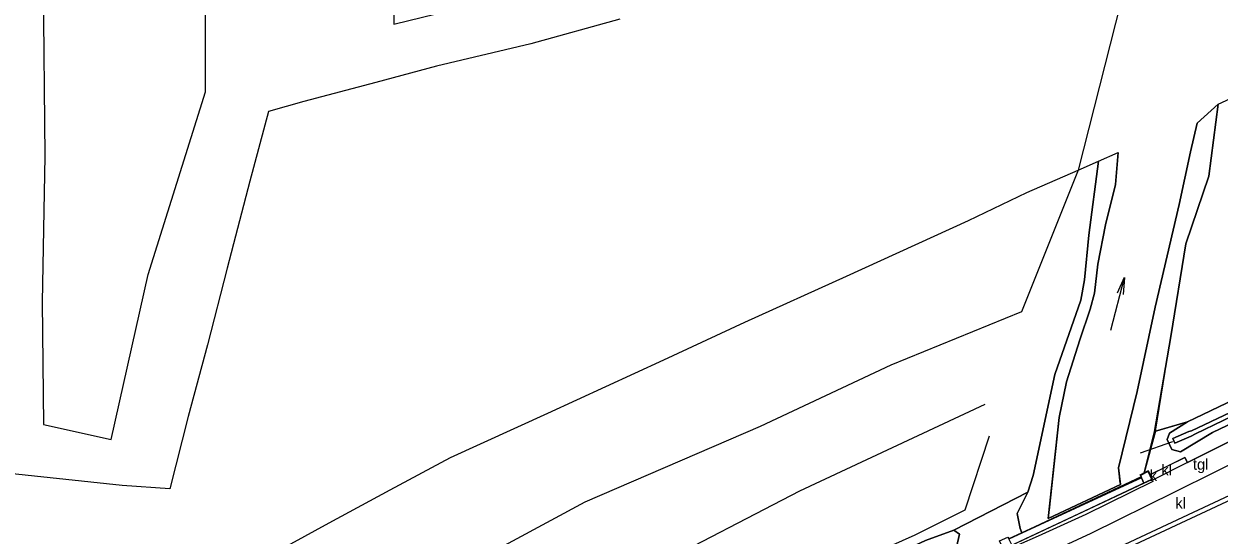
# Model space of a CAD drawing. Extents: x 154825 to 158680, y 370717 to 378075.
# Drawn here: x 157534.8 to 157644.3, y 372802.7 to 372849.4 of the extents above; entities that cross this region are included whole.
import ezdxf

# ---------------------------------------------------------------- set-up
doc = ezdxf.new("R2010")
doc.units = 0
for name, color, linetype in [('bos(vs)', 7, 'Continuous'), ('cultuurscheiding', 7, 'Continuous'), ('duiker lijn', 7, 'Continuous'), ('hoogteverschillijn', 7, 'Continuous'), ('insteek sloot', 7, 'Continuous'), ('kantstreep', 7, 'Continuous'), ('klinkerverharding(vs)', 7, 'Continuous'), ('kolk', 7, 'Continuous'), ('maaiveldlijn algemeen', 7, 'Continuous'), ('maaiveldlijn algemeen - gesloten verharding', 7, 'Continuous'), ('maaiveldlijn algemeen - open verharding', 7, 'Continuous'), ('maaiveldlijn algemeen - tegelverharding', 7, 'Continuous'), ('muur(vs)', 7, 'Continuous'), ('raster - hek', 7, 'Continuous'), ('raster_hekw+inst', 7, 'Continuous'), ('Sloot bodem', 7, 'Continuous'), ('stroomrichting  watergangen', 7, 'Continuous'), ('tegelverh(vs)', 7, 'Continuous'), ('vlak_Grasland', 7, 'Continuous'), ('vlak_Grazige_vegetatie', 7, 'Continuous')]:
    doc.layers.add(name, color=color, linetype=linetype)

msp = doc.modelspace()

# ---------------------------------------------------------------- linework, layer by layer
at = {"layer": 'bos(vs)'}
msp.add_lwpolyline([(157623.23, 372811.7), (157621.02, 372804.94), (157616.45, 372802.64), (157607.48, 372798.66), (157594.37, 372792.37), (157589.88, 372790.37), (157585.87, 372788.62), (157567.97, 372780.57), (157558.91, 372776.64), (157541.92, 372768.79), (157538.52, 372766.1)], dxfattribs=at)
at = {"layer": 'cultuurscheiding'}
msp.add_lwpolyline([(157620, 372803.1), (157626.79, 372806.58)], dxfattribs=at)
at = {"layer": 'duiker lijn'}
msp.add_lwpolyline([(157640.02, 372811.18), (157637.08, 372810.14)], dxfattribs=at)
at = {"layer": 'hoogteverschillijn'}
for points in [[(157536.6, 372852.98), (157536.76, 372837.33), (157536.52, 372823.98), (157536.64, 372812.78), (157542.84, 372811.4), (157546.21, 372826.49), (157551.47, 372843.22), (157551.44, 372857.37)], [(157568.71, 372856.35), (157568.73, 372849.4), (157586.6, 372853.81)], [(157589.42, 372849.87), (157581.27, 372847.62), (157572.62, 372845.55), (157567.06, 372844.07), (157560.48, 372842.33), (157557.26, 372841.41), (157555.53, 372835.04), (157553.46, 372827.09), (157551.67, 372820.05), (157549.9, 372813.51), (157548.22, 372806.9), (157543.85, 372807.19), (157532.06, 372808.44), (157511.61, 372810.6), (157499.58, 372812), (157487.55, 372813.4), (157478.54, 372814.42)], [(157528.08, 372785.12), (157538.48, 372790.7), (157551.21, 372797.56), (157557.07, 372800.63), (157562.8, 372803.78), (157568.39, 372806.8), (157573.92, 372809.75), (157582.83, 372813.82), (157593.46, 372818.69), (157600.86, 372822.13), (157610.17, 372826.36), (157621.34, 372831.45), (157626.69, 372833.99), (157631.39, 372836.05), (157626.21, 372823.09), (157614.24, 372818.21), (157602.28, 372812.59), (157586.22, 372805.66), (157572.57, 372798.3), (157559.35, 372791.47), (157543.19, 372783.22), (157527.98, 372775.61)], [(157532.26, 372769.42), (157543.45, 372775.3), (157553.64, 372780.45), (157564.66, 372785.84), (157576.37, 372791.45), (157592.14, 372799.55), (157605.89, 372806.7), (157622.87, 372814.64)]]:
    msp.add_lwpolyline(points, dxfattribs=at)
at = {"layer": 'insteek sloot'}
for points in [[(157638.48, 372812.15), (157639.88, 372820.84), (157641.24, 372829.32), (157643.35, 372835.51), (157644.23, 372842.08)], [(157626.24, 372802.87), (157626.07, 372803.26), (157625.81, 372804.64), (157626.79, 372806.58), (157627.26, 372808.12), (157629.27, 372817.35), (157631.63, 372824.14), (157631.97, 372826), (157632.37, 372830.09), (157633.26, 372836.87)], [(157689.59, 372835.43), (157691.19, 372835.87), (157691.59, 372835.78), (157692, 372834.72), (157691.48, 372834.35), (157671.74, 372825.02), (157650.28, 372815.17), (157643.7, 372812.04), (157640.77, 372810.28), (157639.96, 372810.48), (157639.54, 372811.41), (157639.75, 372811.99), (157641.4, 372813.01)], [(157592.6, 372790.39), (157592.59, 372789.42), (157593.79, 372788.81), (157606.54, 372794.61), (157615.7, 372798.94), (157620.06, 372800.75), (157620.52, 372802.73), (157620, 372803.1)], [(157620, 372803.1), (157617.4, 372802.16), (157607.86, 372797.75), (157595.04, 372791.65), (157592.6, 372790.39)]]:
    msp.add_lwpolyline(points, dxfattribs=at)
at = {"layer": 'kantstreep'}
msp.add_lwpolyline([(157758.12, 372858.41), (157746.58, 372853.32), (157739.86, 372850.21), (157734.79, 372847.6), (157723.69, 372842.09), (157702.45, 372832.35), (157680.99, 372822.41), (157659.83, 372812.62), (157637.52, 372802.23), (157632.78, 372800), (157617.21, 372792.78), (157595.92, 372782.87), (157569.75, 372770.75), (157543.55, 372758.61), (157517.06, 372746.36), (157486.41, 372732.15), (157469.86, 372724.47), (157454.4, 372717.29), (157430.13, 372706.05), (157404.83, 372694.32), (157376.21, 372681.02), (157354.77, 372671.07), (157328.63, 372658.97)], dxfattribs=at)
at = {"layer": 'maaiveldlijn algemeen'}
msp.add_lwpolyline([(157624.19, 372802.12), (157624.95, 372802.47), (157625.04, 372802.31), (157626.24, 372802.87), (157627.42, 372803.42), (157637.16, 372807.98), (157637.07, 372808.16), (157637.81, 372808.54), (157637.98, 372808.19), (157638.18, 372807.8), (157638.17, 372807.76), (157631.45, 372804.59), (157624.55, 372801.38), (157624.19, 372802.12)], dxfattribs=at)
at = {"layer": 'maaiveldlijn algemeen - gesloten verharding'}
msp.add_lwpolyline([(157485.69, 372732.18), (157486.38, 372732.42), (157516.97, 372746.59), (157543.47, 372758.88), (157569.58, 372771.01), (157595.75, 372783.12), (157617.89, 372793.48), (157648.67, 372807.88)], dxfattribs=at)
at = {"layer": 'maaiveldlijn algemeen - open verharding'}
msp.add_lwpolyline([(157637.98, 372808.19), (157641.17, 372809.76), (157641.42, 372809.29)], dxfattribs=at)
at = {"layer": 'maaiveldlijn algemeen - tegelverharding'}
for points in [[(157641.42, 372809.29), (157646.9, 372812.04)], [(157647.62, 372810.25), (157640.21, 372806.58), (157632.57, 372802.8), (157627.94, 372800.65), (157620.39, 372797.49), (157616.62, 372795.93)], [(157641.42, 372809.29), (157638.2, 372807.68), (157638.24, 372807.57), (157632.1, 372804.53), (157627.74, 372802.54), (157624.12, 372800.97), (157620.9, 372799.66)]]:
    msp.add_lwpolyline(points, dxfattribs=at)
at = {"layer": 'muur(vs)'}
for points in [[(157625.06, 372802.27), (157625.32, 372801.74), (157637.41, 372807.39), (157637.18, 372807.9), (157625.06, 372802.27)], [(157637.41, 372807.4), (157638.14, 372807.74), (157637.8, 372808.47), (157637.1, 372808.12), (157637.41, 372807.4)]]:
    msp.add_lwpolyline(points, dxfattribs=at)
at = {"layer": 'raster - hek'}
for points in [[(157638.48, 372812.15), (157637.44, 372808.35)], [(157641.4, 372813.01), (157638.48, 372812.15)]]:
    msp.add_lwpolyline(points, dxfattribs=at)
at = {"layer": 'raster_hekw+inst'}
msp.add_lwpolyline([(157689.59, 372835.43), (157670.86, 372826.77), (157645.67, 372815.05), (157641.4, 372813.01)], dxfattribs=at)
at = {"layer": 'Sloot bodem'}
for points in [[(157635.25, 372807.39), (157635.1, 372808.82), (157636.81, 372815.78), (157638.44, 372823.52), (157640.64, 372832.92), (157641.68, 372837.73), (157642.29, 372840.35), (157641.68, 372837.73), (157640.64, 372832.92), (157638.44, 372823.52), (157636.81, 372815.78), (157635.1, 372808.82), (157635.26, 372807.28), (157628.65, 372804.16), (157629.65, 372813.42), (157630.33, 372816.67), (157631.54, 372820.53), (157632.48, 372823.33), (157632.88, 372824.79), (157633.21, 372827.44), (157633.9, 372831.03), (157634.81, 372834.75), (157635.05, 372837.67), (157634.81, 372834.75), (157633.9, 372831.03), (157633.21, 372827.44), (157632.88, 372824.79), (157632.48, 372823.33), (157631.54, 372820.53), (157630.33, 372816.67), (157629.65, 372813.42), (157628.73, 372804.93)], [(157691.3, 372835.37), (157691.46, 372835.02), (157670.79, 372825.29), (157649.73, 372815.58), (157642.14, 372811.91), (157641.73, 372811.7), (157640.24, 372811.06), (157640.07, 372811.48), (157641.54, 372812.14), (157641.78, 372812.19), (157649.43, 372815.83), (157670.59, 372825.61), (157691.3, 372835.37)]]:
    msp.add_lwpolyline(points, dxfattribs=at)
at = {"layer": 'stroomrichting  watergangen'}
for p, q in [((157634.39, 372821.4), (157635.64, 372826.24)), ((157635.62, 372826.23), (157634.97, 372824.79)), ((157635.64, 372826.24), (157635.52, 372824.66))]:
    msp.add_line(p, q, dxfattribs=at)
at = {"layer": 'vlak_Grasland'}
for points in [[(157638.22, 372862.99), (157631.39, 372836.05), (157633.26, 372836.87), (157632.37, 372830.09), (157631.97, 372826), (157631.63, 372824.14), (157629.27, 372817.35), (157627.26, 372808.12), (157626.79, 372806.58), (157620, 372803.1), (157617.4, 372802.16), (157607.86, 372797.75), (157595.04, 372791.65), (157592.6, 372790.39), (157588.81, 372788.72), (157585.87, 372787.4), (157568.99, 372779.97), (157559.6, 372775.27), (157542.71, 372767.63), (157538.52, 372766.1), (157534.28, 372764.07)], [(157645.67, 372815.05), (157641.4, 372813.01), (157638.39, 372812.12), (157639.88, 372820.84), (157641.24, 372829.32), (157643.35, 372835.51), (157644.23, 372842.08), (157657.45, 372848.19)]]:
    msp.add_lwpolyline(points, dxfattribs=at)
at = {"layer": 'vlak_Grazige_vegetatie'}
for points in [[(157637.16, 372807.98), (157627.42, 372803.42), (157626.24, 372802.87), (157626.07, 372803.26), (157625.81, 372804.64), (157626.79, 372806.58), (157627.26, 372808.12), (157629.27, 372817.35), (157631.63, 372824.14), (157631.97, 372826), (157632.37, 372830.09), (157633.26, 372836.87), (157635.05, 372837.67), (157634.81, 372834.75), (157633.9, 372831.03), (157633.21, 372827.44), (157632.88, 372824.79), (157632.48, 372823.33), (157631.54, 372820.53), (157630.33, 372816.67), (157629.65, 372813.42), (157628.65, 372804.16), (157635.26, 372807.28), (157635.1, 372808.82), (157636.81, 372815.78), (157638.44, 372823.52), (157640.64, 372832.92), (157641.68, 372837.73), (157642.29, 372840.35), (157644.23, 372842.08), (157643.35, 372835.51), (157641.24, 372829.32), (157639.88, 372820.84), (157638.39, 372812.12), (157637.44, 372808.35), (157637.09, 372808.17)], [(157691.59, 372835.78), (157692, 372834.72), (157691.48, 372834.35), (157671.74, 372825.02), (157650.28, 372815.17), (157643.7, 372812.04), (157640.77, 372810.28), (157639.96, 372810.48), (157639.54, 372811.41), (157639.75, 372811.99), (157641.4, 372813.01), (157645.67, 372815.05), (157670.86, 372826.77), (157689.59, 372835.43), (157691.19, 372835.87)], [(157640.07, 372811.48), (157640.24, 372811.06), (157641.73, 372811.7), (157642.14, 372811.91), (157649.73, 372815.58), (157670.79, 372825.29), (157691.46, 372835.02), (157691.3, 372835.37), (157670.59, 372825.61), (157649.43, 372815.83), (157641.78, 372812.19), (157641.54, 372812.14)], [(157620.52, 372802.73), (157620.06, 372800.75), (157615.7, 372798.94), (157606.54, 372794.61), (157593.79, 372788.81), (157592.59, 372789.42), (157592.6, 372790.39), (157595.04, 372791.65), (157607.86, 372797.75), (157617.4, 372802.16), (157620, 372803.1)]]:
    msp.add_lwpolyline(points, close=True, dxfattribs=at)
for points in [[(157646.9, 372812.04), (157641.42, 372809.29), (157641.17, 372809.76), (157637.99, 372808.17), (157637.81, 372808.54), (157637.44, 372808.35), (157638.39, 372812.12), (157641.4, 372813.01), (157639.75, 372811.99), (157639.54, 372811.41), (157639.96, 372810.48), (157640.77, 372810.28), (157643.7, 372812.04), (157650.28, 372815.17)], [(157620.06, 372800.75), (157620.52, 372802.73), (157620, 372803.1), (157626.79, 372806.58), (157625.81, 372804.64), (157626.07, 372803.26), (157626.24, 372802.87), (157625.04, 372802.31)]]:
    msp.add_lwpolyline(points, dxfattribs=at)

# ---------------------------------------------------------------- texts
at = {"layer": 'klinkerverharding(vs)'}
for p in [(157639.02, 372808.12), (157640.3, 372805.08)]:
    msp.add_text('kl', height=1, dxfattribs=at).set_placement(p)
at = {"layer": 'kolk'}
msp.add_text('k', height=1, dxfattribs=at).set_placement((157637.95, 372807.61))
at = {"layer": 'tegelverh(vs)'}
msp.add_text('tgl', height=1, dxfattribs=at).set_placement((157641.91, 372808.63))

doc.saveas('drawing.dxf')
